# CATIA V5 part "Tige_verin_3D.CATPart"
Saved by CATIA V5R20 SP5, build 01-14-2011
Part number: Tige_verin_3D
Bounding box of the stored display mesh (mm): x -45.156 to 45.156, y 343.45 to 667.296, z 76.279 to 176.251
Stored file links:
  J:\Thinkmotion\Projet IAO\A envoyer\Tige_verin_3D.CATPart
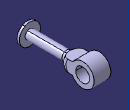
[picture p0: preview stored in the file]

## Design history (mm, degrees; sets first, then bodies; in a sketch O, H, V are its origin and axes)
Body1 (main body)
  Line1: stored without definition
  Line2: stored without definition
  Point1 "V": stored without definition
  Sketch1 on yz-plane, origin (0, 0, 0), H (0, 1, 0), V (0, 0, 1)
    point P1 (343.4498, 128.3861)
    line L1 (353.4498, 173.3927) -> (343.4498, 173.3861)
    line L2 (343.4498, 173.3861) -> (343.4498, 128.3861)
    line L3 (353.4498, 173.3927) -> (353.4498, 148.3927)
    line L4 (353.4498, 148.3927) -> (533.4498, 148.5117)
    line L5 (533.4498, 148.5117) -> (533.4498, 128.5117)
    line L6 (533.4498, 128.5117) -> (343.4498, 128.3861)
    point P7 (343.4498, 128.3861)
    reference projected line E1 (68.4498, 128.2043) -> (233.4498, 128.3134) from Line2
    reference projected point E2 (343.4498, 128.3861) from Point1
    distance L5 L3 = 180
    distance L4 L6 = 20
    distance L4 L1 = 25
    distance L3 L2 = 10
    vertical: L2 V, L3 V, L5 V
    coincidence: P7 P1, L6 E1, P1 E2
  Shaft1: profile Sketch1, axis Line1, angle 360
  Line3: stored without definition
  Line4: stored without definition
  DatumSurface1
  Plane1: type Offset, RefPlane DatumSurface1, Offset 36, reversed
  Line5: stored without definition
  Line6: stored without definition
  Sketch2 on Plane1, origin (-36, 0, 0), H (0, 1, 0), V (0, 0, 1)
    line L1 (533.4498, 103.204) -> (533.4498, 153.204)
    line L2 (533.4498, 153.204) -> (575.2194, 153.204)
    point P3 (575.2194, 153.204)
    line L3 (533.4498, 103.204) -> (572.9749, 103.204)
    arc A1 centre (617.3403, 126.2628) radius 50 from (572.9749, 103.204) to (575.2194, 153.204) ccw
    point P5 (617.3403, 126.2628)
    point P6 (575.2194, 153.204)
    reference projected line E1 (233.933, 128.204) -> (618.933, 128.204) from Line3
    reference projected line E2 (233.933, 128.204) -> (618.933, 128.204) from Line4
    reference intersected line E3 through (533.4498, 0) direction (0, 1) from face of Shaft1 from Sketch1.L5
    circle A2 centre (617.3403, 126.2628) radius 30
    reference projected point E4 (617.3403, 126.2628) from Line5
    reference projected point E5 (617.3403, 126.2628) from Line6
    radius A1 = 50
    distance L3 E1 = 25
    distance L2 E2 = 25
    radius A2 = 30
    vertical: L1 V
    horizontal: L2 H, L3 H
    coincidence: P6 P3, L1 E3, P5 E4, P5 E5
  Pad1: profile Sketch2, direction (1, 0, 0), length 72
  Fillet1: on edge [face of Shaft1 from Sketch1.L4 | face of Pad1 from Sketch2.L1]
  Fillet2: on edge [face of Fillet1 | end face of Pad1]; edge [face of Fillet1 | start face of Pad1]; edge [face of Fillet1 | face of Pad1 from Sketch2.L3]
  Fillet3: radius 5, on edge [face of Pad1 from Sketch2.L2 | face of Pad1 from Sketch2.A1]; edge [face of Pad1 from Sketch2.A1 | face of Pad1 from Sketch2.L3]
